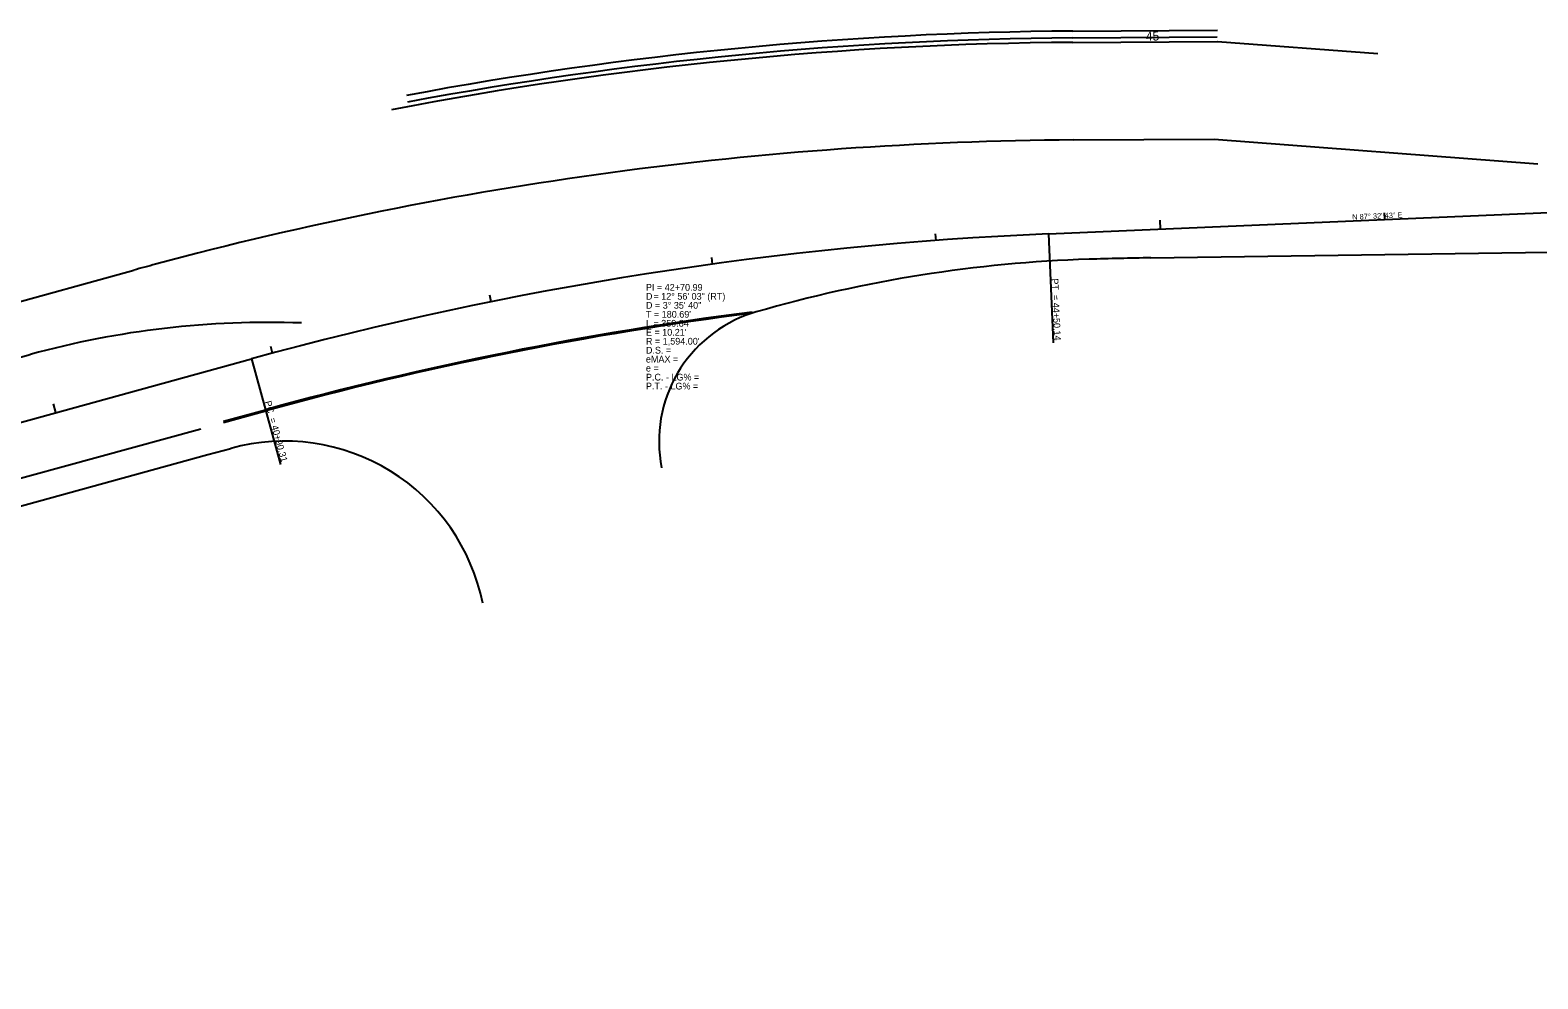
# Model space of a CAD drawing. Extents: x 2004390 to 2007638, y 1136392 to 1138193.
# Drawn here: x 2006322 to 2006993, y 1136943 to 1137366 of the extents above; entities that cross this region are included whole.
import ezdxf

# ---------------------------------------------------------------- set-up
doc = ezdxf.new("R2010")
doc.units = 0
for name, color, linetype in [('RD_HC_Cl', 7, 'Continuous'), ('RD_HC_Data', 7, 'Continuous'), ('RD_HC_Data_Tic', 7, 'Continuous'), ('RD_HC_TX_Sta20', 7, 'Continuous'), ('RD_PD_ConcMed', 7, 'Continuous'), ('RD_PD_Final_TrvlWay', 7, 'Continuous'), ('RD_PD_SideStreet', 7, 'Continuous'), ('RD_XS_Ditch', 7, 'Continuous'), ('RD_XS_MedBWall', 7, 'Continuous')]:
    doc.layers.add(name, color=color, linetype=linetype)

msp = doc.modelspace()

# ---------------------------------------------------------------- linework, layer by layer
at = {"layer": 'RD_HC_Cl'}
for p, q in [((2006775.18, 1137275.34), (2007068.03, 1137287.9)), ((2005534.87, 1136975.91), (2006420.45, 1137219.65))]:
    msp.add_line(p, q, dxfattribs=at)
msp.add_arc((2006843.45, 1135682.8), 1594, 92.45467, 105.38893, dxfattribs=at)
at = {"layer": 'RD_HC_Data'}
for p, q in [((2006775.18, 1137275.34), (2006777.26, 1137226.75)), ((2006420.45, 1137219.65), (2006433.41, 1137172.57))]:
    msp.add_line(p, q, dxfattribs=at)
at = {"layer": 'RD_HC_Data_Tic'}
for p, q in [((2006824.99, 1137277.48), (2006824.82, 1137281.47)), ((2006924.9, 1137281.76), (2006924.77, 1137284.76)), ((2006725.12, 1137272.41), (2006724.9, 1137275.4)), ((2006625.7, 1137261.86), (2006625.29, 1137264.83)), ((2006527.13, 1137245.1), (2006526.53, 1137248.04)), ((2006429.8, 1137222.2), (2006429.03, 1137225.1)), ((2006333.38, 1137195.69), (2006332.32, 1137199.55))]:
    msp.add_line(p, q, dxfattribs=at)
at = {"layer": 'RD_PD_ConcMed'}
msp.add_line((2006307.24, 1137217.54), (2006321.91, 1137221.57), dxfattribs=at)
msp.add_arc((2006428.06, 1136835.91), 400, 87.90965, 105.38893, dxfattribs=at)
at = {"layer": 'RD_PD_Final_TrvlWay'}
for p, q in [((2006786.37, 1137317.15), (2006848.92, 1137317.58)), ((2006848.92, 1137317.58), (2006993, 1137306.57)), ((2006820.7, 1137264.64), (2007054.51, 1137268)), ((2006233.64, 1137222.17), (2006368.1, 1137259.18)), ((2005527.44, 1137002.91), (2006321.91, 1137221.57)), ((2006408.04, 1137191.35), (2006426.82, 1137196.52)), ((2005541.24, 1136952.77), (2006397.86, 1137188.54)), ((2006401.04, 1137176.97), (2006411.22, 1137179.78)), ((2005552.53, 1136943.43), (2006401.04, 1137176.97))]:
    msp.add_line(p, q, dxfattribs=at)
for centre, radius, start, end in [((2006797.46, 1135699.19), 1618, 90.39285, 105.03653), ((2006797.46, 1135699.19), 1618, 105.03653, 105.38893), ((2006812.28, 1136664.31), 600, 91.81897, 106.17842), ((2006843.45, 1135682.8), 1582, 90.8238, 91.81897), ((2006661.82, 1137182.93), 60, 106.17842, 107.98377), ((2006843.45, 1135682.8), 1570, 97.32442, 105.38893), ((2006661.82, 1137182.93), 60, 107.98377, 191.38239), ((2006435.11, 1137093), 90, 11.38239, 105.38893)]:
    msp.add_arc(centre, radius, start, end, dxfattribs=at)
at = {"layer": 'RD_PD_SideStreet'}
msp.add_line((2006407.91, 1137191.83), (2006426.69, 1137197), dxfattribs=at)
msp.add_arc((2006843.45, 1135682.8), 1570.5, 97.32442, 105.38893, dxfattribs=at)
at = {"layer": 'RD_XS_Ditch'}
msp.add_line((2006786.04, 1137365.65), (2006850.48, 1137366.09), dxfattribs=at)
msp.add_arc((2006797.46, 1135699.19), 1666.5, 90.39285, 100.65335, dxfattribs=at)
at = {"layer": 'RD_XS_MedBWall'}
for p, q in [((2006786.06, 1137362.65), (2006850.27, 1137363.09)), ((2006786.07, 1137360.65), (2006850.29, 1137361.09)), ((2006850.43, 1137361.09), (2006921.73, 1137355.64))]:
    msp.add_line(p, q, dxfattribs=at)
for radius, end in [(1663.5, 100.65335), (1661.5, 100.9162)]:
    msp.add_arc((2006797.46, 1135699.19), radius, 90.39285, end, dxfattribs=at)

# ---------------------------------------------------------------- texts
at = {"layer": 'RD_HC_Data'}
for s, height, rotation, p in [('N 87%%d 32\' 43" E', 2.4, 2.45467, (2006910.4, 1137281.64)), ('PT  = 44+50.14', 3, 272.45467, (2006776.54, 1137255.38)), ('PC  = 40+90.31', 3, 285.38893, (2006426.24, 1137200.5))]:
    msp.add_text(s, height=height, rotation=rotation, dxfattribs=at).set_placement(p)
for s, p in [('PI = 42+70.99', (2006596, 1137250)), ('D', (2006596, 1137246)), ('   = 12%%d 56\' 03" (RT)', (2006596, 1137246)), ("T = 180.69'", (2006596, 1137238)), ('D = 3%%d 35\' 40"', (2006596, 1137242)), ("L = 359.84'", (2006596, 1137234)), ("E = 10.21'", (2006596, 1137230)), ("R = 1,594.00'", (2006596, 1137226)), ('eMAX = ', (2006596, 1137218)), ('D.S. = ', (2006596, 1137222)), ('e = ', (2006596, 1137214)), ('P.C. - LG% = ', (2006596, 1137210)), ('P.T. - LG% = ', (2006596, 1137206))]:
    msp.add_text(s, height=3, dxfattribs=at).set_placement(p)
at = {"layer": 'RD_HC_TX_Sta20'}
msp.add_text('45', height=4, rotation=2.45467, dxfattribs=at).set_placement((2006818.59, 1137361.28))

doc.saveas('drawing.dxf')
